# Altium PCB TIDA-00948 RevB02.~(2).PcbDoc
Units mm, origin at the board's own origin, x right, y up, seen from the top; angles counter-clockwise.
Board outline 20 x 25 mm, 2 copper layers (Top Layer, Bottom Layer), stack 1.575 mm thick; 22 components, 8 nets, 38 pads, 0 vias.
Unrouted connection lines stored in the file: 1.
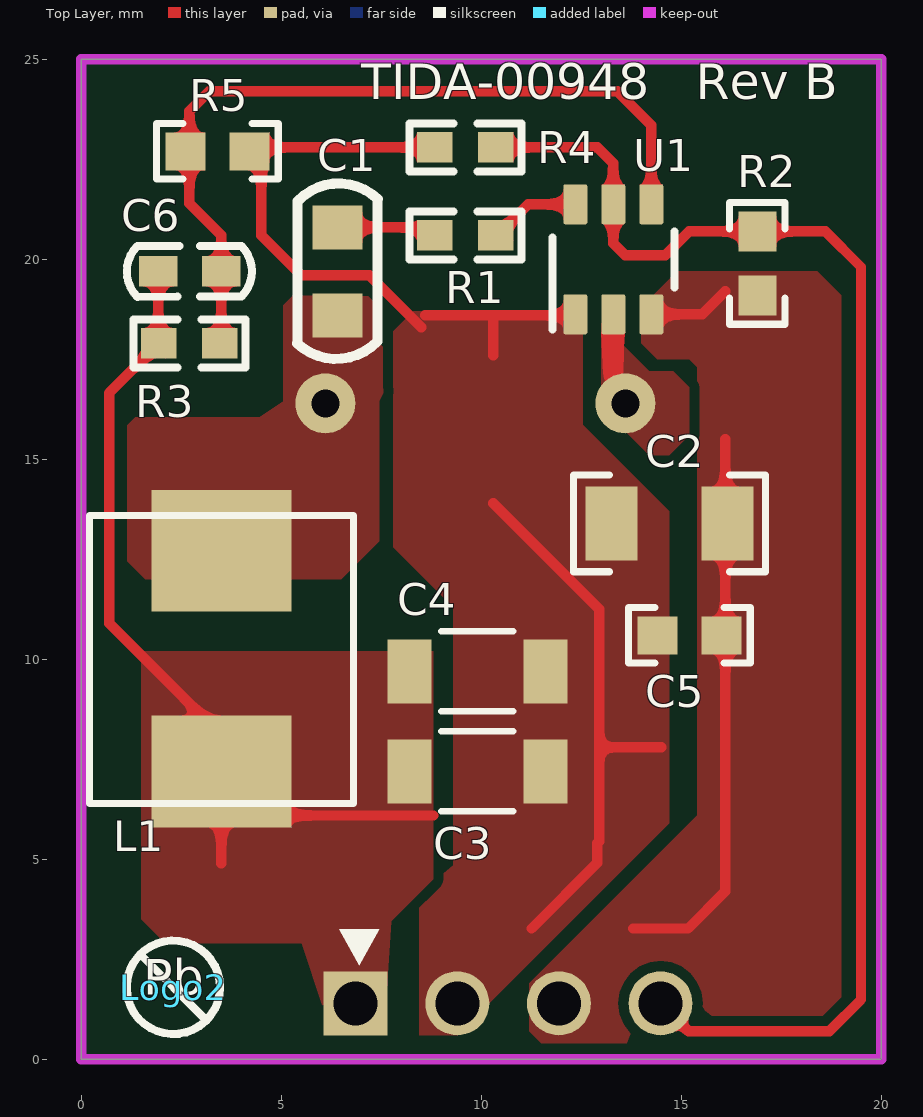
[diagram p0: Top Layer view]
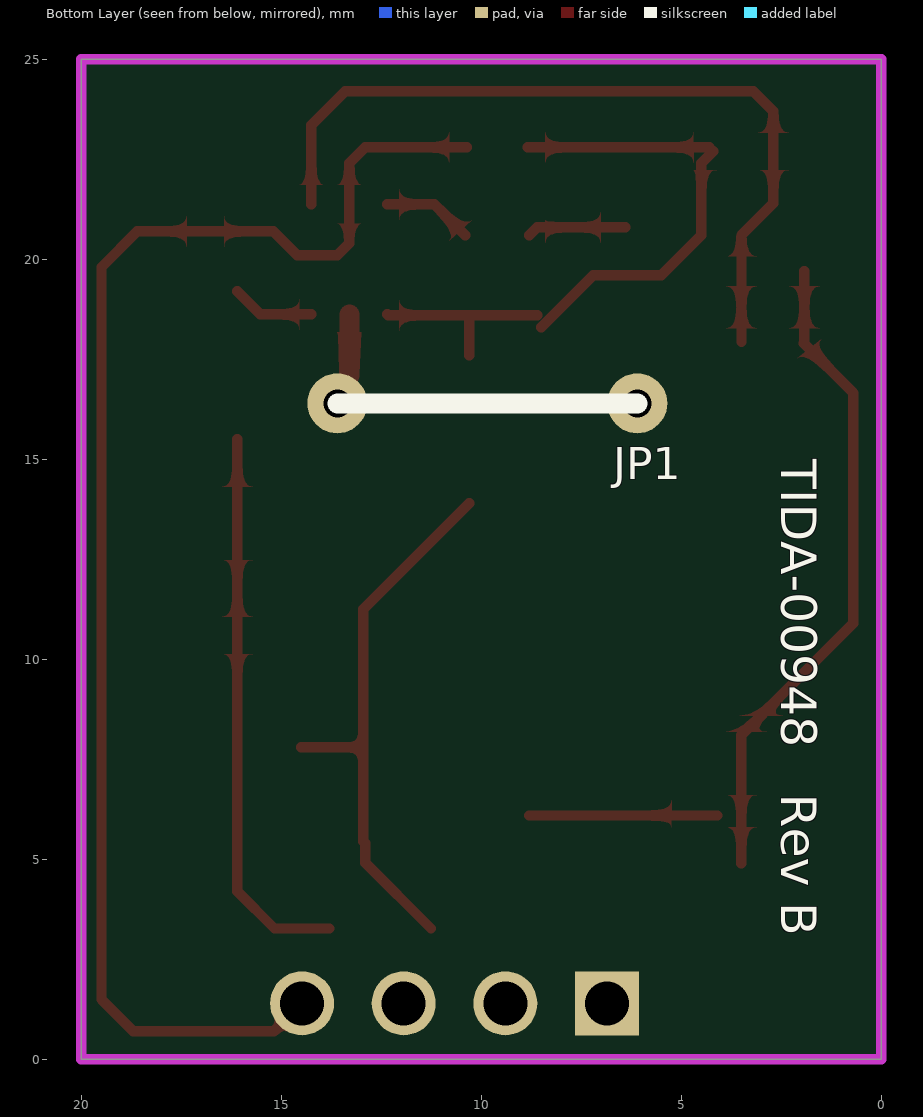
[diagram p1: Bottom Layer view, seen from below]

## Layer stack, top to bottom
Top Solder: solder mask 0.0102, Solder Resist, Dk 3.5
Top Layer: signal copper 0.0356
Dielectric1: core 1.5037, FR-4, Dk 4.8
Bottom Layer: signal copper 0.0356
Bottom Solder: solder mask 0.0102, Solder Resist, Dk 3.5

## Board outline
0,0 0,25 20,25 20,0

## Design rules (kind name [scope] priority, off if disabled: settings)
AcuteAngle [All] p1: minimum=4.50000000000000E+0001 checktracksonly=FALSE
AssemblyTestPointUsage [All] p1: valid=2
Clearance Clearance_Keepouts [((IsTrack Or IsArc) And Not InPoly) And IsFree and IsKeepOut vs ((IsTrack Or IsArc) And Not InPoly) And IsFree and IsKeepOut] p1 off: gap=0
Clearance Clearance_BoardEdge_MountingHoles [OnCopper and InComponentClass('Mounting Holes') vs IsKeepOut] p2 off: gap=1.016
Clearance Clearance_BoardEdge_Poly [OnCopper and InPoly vs IsKeepOut] p3 off: gap=0.635
Clearance Clearance_BoardEdge [OnCopper and Not InComponentClass('Logo') and not InComponentClass('FiducialMark') and not InRegion(1000,500,4000,800) and Not IsKeepout vs IsKeepOut] p4 off: gap=1.905
Clearance Clearance_Poly [InPolygon] p5 off: gap=0.635
Clearance [All] p6: gap=0.254
ComponentClearance ComponentClearance_MountingHoles_FiducialMarks [InComponentClass('Mounting Holes') vs InComponentClass('FiducialMark')] p1: gap=1.27 collisioncheckmode=3 verticalgap=0.254 showdistances=FALSE
ComponentClearance ComponentClearance_Shunt [InComponentClass('Header') vs InComponentClass('Shunt')] p2: gap=0 collisioncheckmode=3 verticalgap=0 showdistances=FALSE
ComponentClearance ComponentClearance_Logo [InComponentClass('Logo')] p3: gap=1.27 collisioncheckmode=3 verticalgap=0.254 showdistances=FALSE
ComponentClearance ComponentClearance_ScrewToNut [(HasFootprint('NY PMS 440 0025 PH')) vs (HasFootprint('Keystone_1902C'))] p4: gap=0.127 collisioncheckmode=3 verticalgap=0.254 showdistances=FALSE
ComponentClearance ComponentClearance_MountingHoles [InComponentClass('Mounting Holes')] p5: gap=6.35 collisioncheckmode=3 verticalgap=2540 showdistances=FALSE
ComponentClearance ComponentClearance_SmallPassives [HasFootprint('0201*') or HasFootprint('0402*') or HasFootprint('0508') or HasFootprint('0603*') or HasFootprint('0612') or HasFootprint('0805*') or HasFootprint('0815*') or HasFootprint('0830*') or HasFootprint('1206*') or HasFootprint('1210*') or HasFootprint('1808*') or HasFootprint('1812*') or HasFootprint('1825*') or HasFootprint('2010*') or HasFootprint('2220*') or HasFootprint('2225*') or HasFootprint('2512*') or HasFootprint('2728*') or HasFootprint('3518*') vs HasFootprint('0201*') or HasFootprint('0402*') or HasFootprint('0508') or HasFootprint('0603*') or HasFootprint('0612') or HasFootprint('0805*') or HasFootprint('0815*') or HasFootprint('0830*') or HasFootprint('1206*') or HasFootprint('1210*') or HasFootprint('1808*') or HasFootprint('1812*') or HasFootprint('1825*') or HasFootprint('2010*') or HasFootprint('2220*') or HasFootprint('2225*') or HasFootprint('2512*') or HasFootprint('2728*') or HasFootprint('3518*')] p6: gap=0.508 collisioncheckmode=3 verticalgap=0.254 showdistances=FALSE
ComponentClearance ComponentClearance_THtoSMT [IsThruComponent vs IsSMTComponent] p7: gap=2.54 collisioncheckmode=3 verticalgap=0.762 showdistances=FALSE
ComponentClearance ComponentClearance_THtoTH [IsThruComponent vs IsThruComponent] p8: gap=3 collisioncheckmode=3 verticalgap=0.762 showdistances=FALSE
ComponentClearance [All] p9: gap=1.016 collisioncheckmode=3 verticalgap=0.254 showdistances=FALSE
DiffPairsRouting [All] p1: maxlimit=2.54 minlimit=0.254 mostfreqgap=0.254 toplayer_minwidth=0.381 toplayer_maxwidth=0.381 toplayer_prefwidth=0.381 bottomlayer_minwidth=0.381 bottomlayer_maxwidth=0.381 bottomlayer_prefwidth=0.381 maxuncoupledlength=25.4
FabricationTestPointUsage TestPointUsage [All] p1: valid=2 allowmultiple=FALSE
FabricationTestpoint Testpoint [All] p1: side=3 testpointundercomponent=TRUE minsize=1.016 maxsize=2.54 preferedsize=1.524 minholesize=0 maxholesize=1.016 preferedholesize=0.813 testpointgrid=0.025 allowsidetop=TRUE allowsidebottom=TRUE usegrid=TRUE gridtolerance=0
FanoutControl Fanout_LCC [IsLCC] p1: bgadir=Out bgaviamode=Centered fanoutstyle=Auto fanoutdirection=Alternating viagrid=0.025 // Fanout_LCC (Default Rule)
FanoutControl Fanout_BGA [IsBGA] p2: bgadir=Out bgaviamode=Centered fanoutstyle=Auto fanoutdirection=Alternating viagrid=0.025 // Fanout_BGA (Default Rule)
FanoutControl Fanout_Default [All] p4: bgadir=Out bgaviamode=Centered fanoutstyle=Auto fanoutdirection=Alternating viagrid=0.025 // Fanout_Default (Default Rule)
FanoutControl Fanout_Small [(CompPinCount < 5)] p5: bgadir=Out bgaviamode=Centered fanoutstyle=Auto fanoutdirection=OutThenIn viagrid=0.025 // Fanout_Small (Default Rule)
HoleSize [All] p1: absolutevalues=TRUE maxlimit=6.375 minlimit=0.203 maxpercent=80.000 minpercent=20.000
MinimumAnnularRing MinimumAnnularRing_ThermalPadVias [IsVia and InAnyComponent] p1: minimumring=0.15
MinimumAnnularRing [All] p2: minimumring=0.229
MinimumSolderMaskSliver MinimumSolderMaskSliver_Logo [InComponentClass('Logo') vs InComponentClass('Logo')] p1: minsoldermaskwidth=0.018
MinimumSolderMaskSliver [All] p2: minsoldermaskwidth=0.1
PlaneConnect [All] p1: planeconnectstyle=Relief reliefexpansion=0.254 reliefentries=4 reliefconductorwidth=0.254 reliefairgap=0.254
PolygonConnect [All] p1: connectstyle=Direct reliefconductorwidth=0.254 reliefentries=4 polygonreliefangle="90 Angle" airgapwidth=0.254
RoutingVias ThermalPadVias [IsVia and InAnyComponent] p1: holewidth=0.2 width=0.5 viastyle="Through Hole" minholewidth=0.2 minwidth=0.5 maxholewidth=0.33 maxwidth=0.6
RoutingVias [All] p2: holewidth=0.406 width=0.864 viastyle="Through Hole" minholewidth=0.2 minwidth=0.66 maxholewidth=1.016 maxwidth=1.651
SilkToBoardRegionClearance [Not ((IsComment or IsDesignator) And (Hide <> 'False')) and not InRegion(1000,500,4000,800)] p1:
SilkToSilkClearance SilkToSilkClearance_Pb-FreeLogo [(HasFootprint('Pb-Free_Overlay_Medium') OR HasFootprint('Pb-Free_Overlay_Small')) vs (HasFootprint('Pb-Free_Overlay_Medium') OR HasFootprint('Pb-Free_Overlay_Small'))] p1: silktosilkclearance=0
SilkToSilkClearance [All] p2: silktosilkclearance=0.102
SilkToSolderMaskClearance SilkToComonentPadClearance [IsPad and InAnycomponent] p1: minsilkscreentomaskgap=0.127 clearancetoexposedcopper=TRUE
SilkToSolderMaskClearance "Silk to Solder Mask Opening" [All] p2: minsilkscreentomaskgap=0.102 clearancetoexposedcopper=FALSE
SolderMaskExpansion [All] p1: expansion=0.05
UnpouredPolygon [All] p1: allowunpoured=FALSE
Width [All] p1: maxlimit=2.54 minlimit=0.152 preferedwidth=0.254 checkconnectedcopper=TRUE
14 further rules are at their usual default settings.

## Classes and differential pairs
component class "TIDA-00948 RevA": C1 C2 C3 C4 C5 C6 JP1 L1 R1 R2 R3 R5 U1
component class Header: JP1
component class AssemblyNote: ZZ2 ZZ3 ZZ4
component class TID_Hardware: H5 H6 H7 H8 Logo2 ZZ2 ZZ3 ZZ4

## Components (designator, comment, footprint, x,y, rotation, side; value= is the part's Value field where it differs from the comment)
C1 "GRM188R71E104KA01D" C/0805/SMT1 6.4,20.7 r270 top
C2 "GRM31CR71E106KA12L" 1206 14.7,13.4 r180 top
C3 "GCM31CR71A226KE02" 1206_190 9.9,7.2 r0 top
C4 "GCM31CR71A226KE02" 1206_190 9.9,9.7 r0 top
C5 "GRM188R71E104KA01D" 0603 15.2,10.6 r180 top
C6 "06033C101KAT2A" C/0603 2.7,19.7 r0 top
H5 "1902C" Keystone_1902C -36.24,59.15 r180 bottom locked
H6 "1902C" Keystone_1902C 79.33,59.15 r180 bottom locked
H7 "1902C" Keystone_1902C -36.24,-18.32 r180 bottom locked
H8 "1902C" Keystone_1902C 79.33,-18.32 r180 bottom locked
JP1 "Comment" JUMP-7.5 6.1,16.4 r0 bottom
L1 "LPS8045B-333MRB" WE-PD-M 3.5,10 r270 top
Logo2 "Pb-Free Symbol" Pb-Free_Overlay_Small 2.3,1.8 r0 top
R1 "CRCW06030000Z0EA" r/0603 9.6,20.6 r180 top
R2 "CRCW0603510KJNEA" 0603 16.9,19.9 r270 top
R3 "CRCW0603100KFKEA" R/0603 2.7,17.9 r180 top
R4 "CRCW0603100KFKEA" R/0603 9.6,22.8 r0 top (schematic designator R3)
R5 "CRCW060313K3FKEA" 0603 3.4,22.7 r180 top
U1 "TPS54202DDCR" DDC0006A_N 13.3,20 r90 top
ZZ2 "These assemblies are ESD sensitive, ESD precautions shall be observed." AssemblyNote -36.621,73.859 r0 top
ZZ3 "These assemblies must be clean and free from flux and all contaminants. Use of no clean flux is not acceptable." AssemblyNote -36.621,71.61 r0 top
ZZ4 "These assemblies must comply with workmanship standards IPC-A-610 Class 2, unless otherwise specified." AssemblyNote -36.621,69.361 r0 top

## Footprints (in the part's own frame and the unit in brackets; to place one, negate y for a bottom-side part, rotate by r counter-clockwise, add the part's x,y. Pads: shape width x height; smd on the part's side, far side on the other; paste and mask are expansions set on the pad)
0603 [mm] "0603 from SM-752 data"
  rect 1x0.95 smd: 1(-0.8,0) 2(0.8,0)
  silkscreen extent -1.52,-0.69 1.52,0.69, body extent -0.87,-0.47 0.87,0.47, height 1
1206 [mm] "1206 from SM-752 data"
  rect 1.3x1.85 smd: 1(-1.45,0) 2(1.45,0)
  silkscreen extent -2.4,-1.21 2.4,1.21, body extent -1.7,-0.9 1.7,0.9, height 1.35
1206_190 [mm] "1206_190"
  rect 1.1x1.6 smd: 1(-1.7,0) 2(1.7,0)
  silkscreen extent -0.9,-1 0.9,1, body extent -1.75,-0.95 1.75,0.95, height 1.9
AssemblyNote [mm] "Assembly Note"
C/0603 [mil]
  rect 38x30 smd: 1(-30.52,0.06) 2(31.48,0.06)
  silkscreen extent -62,-25 62,25
C/0805/SMT1 [mm]
  rect 1.1x1.25 smd: 1(-0.1,0) 2(2.1,0)
  silkscreen extent -1.19,-1 3.19,1.01
DDC0006A_N [mm]
  rrect17% 1x0.6 smd: 1(-1.375,0.95) 2(-1.375,0) 3(-1.375,-0.95) 4(1.375,-0.95) 5(1.375,0) 6(1.375,0.95)
  silkscreen extent -1.75,-1.52 0.7,1.53, body extent -1.43,-1.48 1.43,1.49, height 0.92
JUMP-7.5 [mm]
  round 1.5 hole 0.7: 1(0,0) 2(7.5,0)
  silkscreen extent 0,0 7.5,0
Keystone_1902C [mm] "Hex Standoff, 4-40 threaded, nylon"
  body extent -3.68,-3.2 3.71,3.2, height 12.73
Pb-Free_Overlay_Small [mm]
  silkscreen extent -1.16,-1.17 1.17,1.17
r/0603 [mil]
  rect 35x30 smd: 1(-30,0) 2(30,0)
  silkscreen extent -55,-24 55,24
R/0603 [mil]
  rect 35x30 smd: 1(-30,0) 2(30,0)
  silkscreen extent -55,-24 55,24
WE-PD-M [mm] "Wurth Elektronik recommended land pattern, 2008-01-04"
  rect 2.4x3.5 smd: 1(-3.035,0) 2(3.004,0)
  silkscreen extent -3.6,-3.3 3.6,3.3, body extent -3.81,-3.84 3.81,3.79, height 4.5

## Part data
C1 C5: "CAP, CERM, 0.1 μF, 25 V, +/- 10%, X7R, 0603"
C2: "CAP, CERM, 10 μF, 25 V, +/- 10%, X7R, 1206"
C3 C4: "CAP, CERM, 22 μF, 10 V, +/- 10%, X7R, AEC-Q200 Grade 1, 1206_190"
C6: "CAP, CERM, 100 pF, 25 V, +/- 10%, X7R, 0603"
H5 H6 H7 H8: "Standoff, Hex, 0.5\"L #4-40 Nylon"
L1: "Inductor, Shielded, Ferrite, 33 μH, 1.2 A, 0.121 ohm, SMD"
Logo2: library part Pb-Free
R1: "RES, 0, 5%, 0.1 W, 0603"
R2: "RES, 510 k, 5%, 0.1 W, 0603"
R3 R4: "RES, 100 k, 1%, 0.1 W, 0603"
R5: "RES, 13.3 k, 1%, 0.1 W, 0603"
U1: "4.5-V TO 28-V INPUT, 2-A OUTPUT, EMI FRIENDLY SYNCHRONUOUS STEP-DOWN CONVERTOR, DDC0006A"
ZZ2 ZZ3 ZZ4: library part AssemblyNote

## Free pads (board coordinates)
  rect 3.5x2 smd: 0(3.5,7.6)
  rect 3.5x2.4 smd: 0(3.5,12.4)
  rect 1.6x1.6 hole 1.1: 0(6.86,1.4)
  round 1.6 hole 1.1: 0(9.4,1.4) 0(11.94,1.4) 0(14.48,1.4)

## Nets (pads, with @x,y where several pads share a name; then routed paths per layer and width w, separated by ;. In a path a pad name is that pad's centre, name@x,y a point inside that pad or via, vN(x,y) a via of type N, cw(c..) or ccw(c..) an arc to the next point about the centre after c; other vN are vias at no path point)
+5V: C3.1 C4.1 C6.1 L1.2 pad.0@3.5,7.6 pad.0@6.86,1.4 R3.2 | length 21.2
  Top Layer w0.254: R3.2@1.925,17.913 C6.1 ; R3.2 0.7,16.662 0.7,10.9 3.5,8.1 3.5,4.896 ; L1.2@4.103,6.097 8.804,6.097
EN: pad.0@14.48,1.4 R2.1 R4.2 U1.5 | length 36
  Top Layer w0.254: R4.2 12.9,22.8 13.3,22.4 U1.5 13.3,20.4 13.6,20.1 14.6,20.1 15.2,20.7 R2.1 18.6,20.7 19.492,19.808 19.492,1.492 18.7,0.7 15.18,0.7 pad.0@14.48,1.4
GND: C2.2 C3.2 C4.2 C5.2 pad.0@9.4,1.4 R4.1 R5.1 U1.1 | length 30.3
  Top Layer w0.254: R5.1 4.5,22.4 4.5,20.6 5.5,19.6 7.2,19.6 8.5,18.3 ; R5.1@4.3,22.8 R4.1 ; 8.6,18.6 12.325,18.6 U1.1 ; 10.3,13.9 12.95,11.25 12.95,7.8 ; 10.3,17.6 10.3,18.5 ; 11.258,3.27 12.9,4.912 12.9,5.4 ; 12.95,5.45 12.95,7.8 ; 14.5,7.8 12.95,7.8
NetC1_1: C1.1 R1.2 | length 2.5
  Top Layer w0.254: C1.1 8.6,20.8 R1.2@8.8,20.6
NetC1_2: C1.2 JP1.1 JP1.2 L1.1 pad.0@3.5,12.4 U1.2 | length 1.5
  Top Layer w0.5: 13.3,17.1 U1.2
NetC6_2: C6.2 R3.1 R5.2 U1.4 | length 20.2
  Top Layer w0.254: R3.1@3.5,17.938 C6.2 3.5,20.6 2.7,21.4 2.7,23.7 3.2,24.2 13.4,24.2 14.25,23.35 U1.4
NetR1_1: R1.1 U1.6 | length 2.3
  Top Layer w0.254: R1.1@10.4,20.6 11.175,21.375 U1.6
VIN: C2.1 C5.1 pad.0@11.94,1.4 R2.2 U1.3 | length 16.1
  Top Layer w0.254: 13.798,3.27 15.17,3.27 16.1,4.2 16.1,7.8 16.1,15.5 ; U1.3 15.525,18.625 16.1,19.2

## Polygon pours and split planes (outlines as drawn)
VIN on Top Layer "Top Layer-No Net 1" (solid, remove dead copper, pour order 9): 14,19 14,17.9 14.3,17.6 14.4,17.5 15.2,17.5 15.4,17.3 15.4,15.9 15.4,6.1 14.6,5.3 11.2,1.9 11.2,0.7 11.5,0.4 18.3,0.4 18.4,0.4 19,1 19,19.1 18.7,19.4 18.4,19.7 15.7,19.7 14.9,19.7 14.3,19.1
GND on Top Layer "Top Layer-No Net" (solid, remove dead copper, pour order 6): 12.535,15.865 14.7,13.7 14.7,8.2 14.7,6.2 14.7,5.9 12.8,4 9.4,0.6 8.449,0.6 8.449,4.049 9,4.6 9.3,4.858 9.3,11.3 7.8,12.8 7.8,18.2 8.3,18.7 12.535,18.7
NetC1_2 on Top Layer "Top Layer-No Net 2" (solid, remove dead copper, pour order 7): 7.45,16.45 7.45,12.95 6.5,12 1.6,12 1.15,12.45 1.15,15.85 1.35,16.05 3.75,16.05 4.45,16.05 5.05,16.45 5.05,18.85 5.3,19.1 7.35,19.073 7.35,18 7.55,17.8 7.55,15.85
NetC1_2 on Top Layer "Top Layer-No Net 3" (solid, remove dead copper, pour order 8): 13.5,18.4 13.5,17.9 13.8,17.6 14.2,17.2 14.6,17.2 14.8,17.2 15,17 15.2,16.8 15.2,16.2 15.2,15.6 14.9,15.3 14.7,15.1 14.3,15.1 14.2,15.1 13.7,15.6 13,16.3 13,17.5 13,18.4
+5V on Top Layer "Top Layer-No Net 4" (solid, remove dead copper, pour order 10): 8.8,10.2 8.8,4.5 7.75,3.45 7.621,1.547 6.021,1.356 5.507,2.9 2.1,2.9 1.5,3.5 1.5,10.2

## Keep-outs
Keep-Out Layer:
  lines w0.254: -41.447,64.23 cw(c-41.32,64.23) -41.32,64.357 ccw(c-41.32,64.23) -41.447,64.23 ; 0,0 0,25 20,25 20,0 0,0

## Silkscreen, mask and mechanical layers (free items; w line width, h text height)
Top Overlay:
  region: 6.95,2.35 7.45,3.25 6.45,3.25
  text "TIDA-00948   Rev B" at 7,23.7 h1.52
Bottom Overlay:
  text "TIDA-00948   Rev B" at 2.8,15 h1.52 r90
Top Paste:
  text ".Layer_Name" at -26.664,-45.206 h1.52
Bottom Paste:
  text ".Layer_Name" at -26.664,-45.206 h1.52
Top Solder:
  lines w0.8: 2.1,3.6 4.1,3.6 ; 3,4.8 5,4.8 ; 5.3,3.8 7.3,3.8 ; 6.25,4.75 8.25,4.75 ; 8.5,15.6 8.5,17.6 ; 8.7,12.5 8.7,14.5 ; 9.6,16.1 9.6,18.1 ; 9.7,2.4 9.7,4.4 ; 10,13 10,15 ; 10.8,3.6 10.8,5.6 ; 10.9,16.2 10.9,18.2 ; 11.6,13.09 11.6,15.09 ; 12,3.8 12,5.8 ; 13.1,6 13.1,9.3 ; 14.2,6.2 14.2,8.2 ; 16,2.2 16,5.4 ; 16.1,6.7 16.1,8.7 ; 17.1,2 17.1,5.2 ; 17.2,7.3 17.2,9.3 ; 17.2,15.5 17.2,17.5 ; 18.3,2 18.3,3.9 ; 18.3,9.3 18.3,11.3 ; 18.4,5.5 18.4,7.5 ; 18.4,13 18.4,15 ; 18.4,16.7 18.4,18.7
  lines w1: 12.9,2.5 14.9,4.5
Bottom Solder:
  text ".Layer_Name" at -26.664,-45.206 h1.52
Drill Guide:
  text ".Layer_Name" at -26.664,-45.206 h1.52
M1 Board Outline:
  lines w0.254: -41.32,-23.4 84.41,-23.4 84.41,64.23 -41.32,64.23 -41.32,-23.4
  text ".Layer_Name" at -26.664,-45.206 h1.52
M2 Board Dimensions:
  rectangle: -38.145,-33.56 -28.62,-30.385
  rectangle: -41.32,-30.385 -38.145,-27.21
  lines w0.178: -41.32,-30.385 -15.92,-30.385 ; -38.145,-33.56 -38.145,-27.21 ; -34.97,-33.56 -34.97,-27.21 ; -28.62,-33.56 -28.62,-27.21 ; -22.27,-33.56 -22.27,-27.21 ; -41.32,-33.56 -41.32,-27.21 -15.92,-27.21 -15.92,-33.56 -41.32,-33.56
  text ".Layer_Name" at -26.664,-45.206 h1.52
M3 3D STEP Top:
  text ".Layer_Name" at -26.664,-45.206 h1.52
M4 3D STEP Bottom:
  text ".Layer_Name" at -26.664,-45.206 h1.52
M5 Assembly Top:
  lines w0.254: -48.737,-47.026 118.903,-47.026 ; -48.737,-41.862 118.954,-41.862 ; -48.737,-36.697 -48.737,-52.191 52.99,-52.191 118.954,-52.191 118.954,-36.697 -48.724,-36.697 -48.724,-52.191 -8.706,-52.191 ; 13.874,-52.191 13.874,-36.697 ; 46.056,-41.862 46.056,-36.697 ; 67.392,-41.862 67.392,-36.697 ; 83.191,-52.356 83.191,-47.204
  text "COMPONENTS MARKED 'DNP' SHOULD NOT BE POPULATED." at -12.021,-31.49 h1.52
  text "ASSEMBLY VARIANT:" at -12.034,-34.424 h1.52
  text ".VariantName" at 14.281,-34.424 h1.52
  text "PCB VIEWED FROM TOP SIDE" at -47.124,-40.054 h1.52
  text "BOARD #:" at 15.779,-40.054 h1.52
  text ".PRJ_Number" at 29.635,-40.054 h1.52
  text "REV:" at 51.085,-40.054 h1.52
  text ".PCB_Rev" at 58.489,-40.054 h1.52
  text "SVN REV:" at 72.37,-40.054 h1.52
  text ".VersionControl_RevNumber" at 85.223,-40.054 h1.52
  text "TID #:" at 15.779,-45.219 h1.52
  text ".TID" at 29.635,-45.219 h1.52
  text "PLOT NAME =" at -47.124,-50.434 h1.52
  text ".plot_File_Name" at -26.664,-50.434 h1.52
  text "GENERATED    :" at 15.83,-50.434 h1.52
  text ".Print_Date" at 37.915,-50.434 h1.52
  text ".Print_Time" at 56.432,-50.434 h1.52
  text "TEXAS INSTRUMENTS" at 88.55,-50.434 h1.52
M6 Assembly Bottom:
  lines w0.254: -48.75,-41.874 118.941,-41.874 ; -48.699,-47.039 118.941,-47.039 ; -12.986,-52.369 -12.986,-47.217 ; 2.812,-41.874 2.812,-36.71 ; 24.148,-41.874 24.148,-36.71 ; 56.33,-52.204 56.33,-36.71 ; 78.911,-52.204 118.929,-52.204 118.929,-36.71 -48.75,-36.71 -48.75,-52.204 17.214,-52.204 118.941,-52.204 118.941,-36.71
  text "COMPONENTS MARKED 'DNP' SHOULD NOT BE POPULATED." at 113.671,-31.477 h1.52
  text ".VariantName" at 87.153,-34.424 h1.52
  text "ASSEMBLY VARIANT:" at 113.544,-34.424 h1.52
  text ".VersionControl_RevNumber" at -15.018,-40.067 h1.52
  text "SVN REV:" at -2.166,-40.067 h1.52
  text ".PCB_Rev" at 11.715,-40.067 h1.52
  text "REV:" at 19.119,-40.067 h1.52
  text ".PRJ_Number" at 40.57,-40.067 h1.52
  text "BOARD #:" at 54.425,-40.067 h1.52
  text "PCB VIEWED FROM BOTTOM SIDE" at 117.328,-40.067 h1.52
  text ".TID" at 40.57,-45.231 h1.52
  text "TID #:" at 54.425,-45.231 h1.52
  text "TEXAS INSTRUMENTS" at -18.346,-50.447 h1.52
  text ".Print_Time" at 13.773,-50.447 h1.52
  text ".Print_Date" at 32.289,-50.447 h1.52
  text "GENERATED    :" at 54.374,-50.447 h1.52
  text ".plot_File_Name" at 96.869,-50.447 h1.52
  text "PLOT NAME =" at 117.328,-50.447 h1.52
M9 Title Sheet:
  drawing of 57 lines, arcs and shapes, not listed
  text "1" at -22.528,180.727 h1.78
  text "2" at 40.862,180.727 h1.78
  text "3" at 104.091,180.727 h1.78
  text "4" at 167.76,180.727 h1.78
  text "5" at 231.235,180.727 h1.78
  text "6" at 294.862,180.727 h1.78
  text "A" at -51.899,151.695 h1.78
  text "A" at 324.021,151.695 h1.78
  text "B" at -51.899,91.243 h1.78
  text "B" at 324.021,91.243 h1.78
  text "C" at -51.899,30.918 h1.78
  text "C" at 324.021,30.918 h1.78
  text "PROJECT TITLE:" at 246.805,-16.351 h1.14
  text "TIDA-00948" at 248.075,-19.738 h1.78
  text "DESIGNED FOR:" at 246.805,-23.997 h1.14
  text ".PRJ_Customer" at 248.075,-27.553 h1.78
  text "D" at -51.899,-29.28 h1.78
  text "D" at 324.021,-29.28 h1.78
  text "FILE NAME:" at 246.805,-31.617 h1.14
  text ".PCB_File_Name_No_Path" at 248.075,-34.665 h1.78
  text "Texas Instruments (TI) and/or its licensors do not warrant the accuracy or completeness of this specification" at 120.58,-38.776 h1.14
  text "ENGINEER:" at 246.805,-38.983 h1.14
  text "LAYOUT BY:" at 285.032,-38.983 h1.14
  text "or any information contained therein. TI and/or its licensors do not warrant that this design will meet" at 119.437,-41.637 h1.14
  text "Jason Tao" at 248.075,-42.92 h1.78
  text "Jason Tao" at 286.315,-42.92 h1.78
  text "the specifications, will be suitable for your application or fit for any particular purpose, or will operate in" at 119.437,-44.499 h1.14
  text ".Layer_Name" at -26.664,-45.206 h1.52
  text "ALTIUM DESIGNER VERSION:" at 285.032,-46.857 h1.14
  text "an implementation. TI and/or its licensors do not warrant that the design is production worthy. You should" at 119.437,-47.361 h1.14
  text "completely validate and test your design implementation to confirm the system functionality for your application." at 120.58,-50.222 h1.14
  text ".print_Scale" at 248.075,-50.243 h1.78
  text ".Application_BuildNumber" at 286.315,-50.243 h1.78
  text "1" at -22.528,-55.493 h1.78
  text "2" at 40.862,-55.493 h1.78
  text "3" at 104.091,-55.493 h1.78
  text "4" at 167.76,-55.493 h1.78
  text "5" at 231.235,-55.493 h1.78
  text "6" at 294.862,-55.493 h1.78
M10 Fab Notes:
  drawing of 173 lines, arcs and shapes, not listed
  text "DESIGN INFORMATION" at 273.056,134.105 h1.52
  text "MIN. TRACK WIDTH:" at 256.684,129.533 h1.52
  text "8" at 284.529,129.533 h1.52
  text "MIL" at 288.46,129.533 h1.52
  text "MIN. CLEARANCE:" at 256.684,126.181 h1.52
  text "0.2" at 283.005,126.181 h1.52
  text "mm" at 288.46,126.181 h1.52
  text "MIN. VIA PAD SIZE:" at 256.684,122.828 h1.52
  text "24" at 283.767,122.828 h1.52
  text "MIL" at 288.46,122.828 h1.52
  text "0.05mm (2MIL)" at 274.337,119.228 h1.52
  text "MINIMUM ANNULAR RING" at 248.322,119.12 h1.52
  text "EXTERNAL" at 292.321,119.12 h1.52
  text "PER" at 253.402,116.122 h1.52
  text "IPC-D-275 CLASS 2 LEVEL C" at 258.99,116.122 h1.52
  text "MIL, HOLES" at 296.791,113.27 h1.52
  text "+/-" at 286.823,113.252 h1.52
  text "+/-" at 308.514,113.252 h1.52
  text "REGISTRATION TOLERANCES:" at 248.322,113.125 h1.52
  text "METAL" at 278.796,113.125 h1.52
  text "5" at 293.432,113.125 h1.52
  text "3" at 314.59,113.125 h1.52
  text "MIL" at 317.543,113.125 h1.52
  text "+/-" at 308.514,110.255 h1.52
  text "HOLE SIZE TOLERANCE (UNLESS OTHERWISE SPECIFIED):" at 248.322,110.128 h1.52
  text "3" at 314.59,110.128 h1.52
  text "MIL" at 317.543,110.128 h1.52
  text "MATERIAL:" at 246.423,104.808 h1.52
  text "FR-4 High Tg" at 271.479,101.243 h1.52
  text "FR-408" at 257.116,101.025 h1.52
  text "OTHER" at 294.911,101.025 h1.52
  text "X" at 267.544,100.933 h1.52
  text "62 MIL (1.6mm) +/-10%" at 265.247,96.892 h1.52
  text "THICKNESS:" at 248.322,96.784 h1.52
  text "X" at 261.991,96.784 h1.52
  text "OTHER" at 297.883,96.784 h1.52
  text "TOLERANCE:" at 248.322,92.77 h1.52
  text "X" at 269.64,92.77 h1.52
  text "ANSI IPC-6012 TYPE 3 CLASS 2" at 274.389,92.77 h1.52
  text "OTHER +/-" at 274.388,88.808 h1.52
  text "BOW & TWIST:" at 248.322,84.82 h1.52
  text "X" at 269.64,84.82 h1.52
  text "ANSI IPC-6012 TYPE 3 CLASS 2" at 274.389,84.82 h1.52
  text "OTHER +/-" at 274.388,80.794 h1.52
  text "DRILLING:" at 246.423,77.276 h1.52
  text "REFERENCE:" at 248.322,74.305 h1.52
  text "X" at 264.787,74.305 h1.52
  text "AS SHOWN" at 269.537,74.305 h1.52
  text "X" at 287.672,74.305 h1.52
  text "NC_DRILL FILES" at 291.152,74.305 h1.52
  text "PTH MIN COPPER THICKNESS:" at 248.322,70.291 h1.52
  text "X" at 282.618,70.291 h1.52
  text "1MIL" at 286.098,70.291 h1.52
  text "OTHER" at 298.721,70.291 h1.52
  text "BOARD FINISH:" at 246.423,66.253 h1.52
  text "SILKSCREEN:" at 250.365,63.256 h1.52
  text "X" at 274.464,63.256 h1.52
  text "TOP" at 277.665,63.256 h1.52
  text "X" at 287.418,63.256 h1.52
  text "BOTTOM" at 290.644,63.256 h1.52
  text "SILKSCREEN COLOR:" at 250.365,59.014 h1.52
  text "X" at 274.438,59.014 h1.52
  text "WHITE" at 277.665,59.014 h1.52
  text "OTHER" at 290.644,59.014 h1.52
  text "X" at 277.766,54.97 h1.52
  text "GREEN" at 280.992,54.97 h1.52
  text "OTHER" at 296.689,54.97 h1.52
  text "SOLDER RESIST COLOR:" at 250.365,54.696 h1.52
  text "X" at 277.766,50.652 h1.52
  text "MATTE" at 280.992,50.652 h1.52
  text "SEMI-GLOSS" at 296.678,50.636 h1.52
  text "IMMERSION GOLD (ENIG)" at 273.372,45.864 h1.52
  text "ENEPIG" at 307.346,45.78 h1.52
  text "SURFACE FINISH:" at 246.423,45.755 h1.52
  text "X" at 268.624,45.755 h1.52
  text "IMM. TIN/SILVER OR EQUIV" at 254.793,41.767 h1.52
  text "OTHER" at 291.152,41.767 h1.52
  text "ARRAY/PANEL:" at 246.423,37.221 h1.52
  text "CUT AND TRIM PER M1 BOARD OUTLINE" at 273.372,37.112 h1.52
  text "N.C. ROUTE" at 273.372,33.258 h1.52
  text "X" at 290.619,33.258 h1.52
  text "V. SCORE" at 295.369,33.258 h1.52
  text "CERTIFICATION:" at 246.423,29.778 h1.52
  text "MATERIALS AND WORKMANSHIP FOR ALL PCBS" at 264.838,29.778 h1.52
  text "TO MEET OR EXCEED THE REQUIREMENTS OF:" at 264.838,27.289 h1.52
  text "X" at 255.351,23.822 h1.52
  text "ANSI IPC-A-600F CLASS ->" at 258.882,23.822 h1.52
  text "X" at 300.514,23.822 h1.52
  text "2" at 303.535,23.822 h1.52
  text "1" at 295.534,23.784 h1.52
  text "3" at 312.526,23.784 h1.52
  text "X" at 276.028,19.771 h1.52
  text "RoHS" at 279.506,19.771 h1.52
  text "OTHER" at 295.874,19.771 h1.52
  text "PER ORDER" at 305.96,19.771 h1.52
  text "ALL BOARDS MUST MEET OR EXCEED UL94-V0 REQUIREMENTS." at 247.122,15.564 h1.52
  text "PCB MUST BEAR THE UL94V-0 UL REGISTERED MATERIAL ID NUMBER" at 247.122,12.516 h1.52
  text "ADDITIONAL REQUIREMENTS:" at 246.423,8.112 h1.52
  text "MICROSECTION:" at 248.322,5.191 h1.52
  text "YES" at 271.328,5.191 h1.52
  text "REQUIRED" at 293.21,1.225 h1.52
  text "BARE BOARD ELEC. TEST:" at 248.322,1.153 h1.52
  text "NONE" at 281.488,1.153 h1.52
  text "X" at 289.984,1.153 h1.52
  text "PER ORDER" at 308.246,1.153 h1.52
  text ".Layer_Name" at -26.664,-45.206 h1.52
M11 Gerber Information:
  lines w0.254: -48.737,-47.026 118.903,-47.026 ; -48.737,-41.862 118.954,-41.862 ; -48.737,-36.697 -48.737,-52.191 52.99,-52.191 118.954,-52.191 118.954,-36.697 -48.724,-36.697 -48.724,-52.191 -8.706,-52.191 ; 13.874,-52.191 13.874,-36.697 ; 46.056,-41.862 46.056,-36.697 ; 67.392,-41.862 67.392,-36.697 ; 83.191,-52.356 83.191,-47.204
  text "ALL ARTWORK VIEWED FROM TOP SIDE" at -47.124,-40.054 h1.52
  text "BOARD #:" at 15.779,-40.054 h1.52
  text ".PRJ_Number" at 29.635,-40.054 h1.52
  text "REV:" at 51.085,-40.054 h1.52
  text ".PCB_Rev" at 58.489,-40.054 h1.52
  text "SVN REV:" at 72.37,-40.054 h1.52
  text ".VersionControl_RevNumber" at 85.223,-40.054 h1.52
  text "LAYER NAME =" at -47.124,-45.206 h1.52
  text "TID #:" at 15.779,-45.219 h1.52
  text ".TID" at 29.635,-45.219 h1.52
  text "PLOT NAME =" at -47.124,-50.434 h1.52
  text ".plot_File_Name" at -26.664,-50.434 h1.52
  text "GENERATED    :" at 15.83,-50.434 h1.52
  text ".Print_Date" at 37.915,-50.434 h1.52
  text ".Print_Time" at 56.432,-50.434 h1.52
  text "TEXAS INSTRUMENTS" at 88.55,-50.434 h1.52
M12 Stackup:
  drawing of 191 lines, arcs and shapes, not listed
  text "Layer" at 207.361,175.482 h1.52
  text "Name" at 217.772,175.482 h1.52
  text "Material" at 241.388,175.482 h1.52
  text "Thickness" at 263.226,175.482 h1.52
  text "Constant" at 279.732,175.482 h1.52
  text "Board Layer Stack" at 294.206,175.482 h1.52
  text "1" at 207.361,172.434 h1.52
  text "Top Overlay" at 217.772,172.434 h1.52
  text "2" at 207.361,169.386 h1.52
  text "Top Solder" at 217.772,169.386 h1.52
  text "Solder Resist" at 241.388,169.386 h1.52
  text "0.40mil" at 263.226,169.386 h1.52
  text "3.5" at 279.732,169.386 h1.52
  text "3" at 207.361,166.338 h1.52
  text "Top Layer" at 217.772,166.338 h1.52
  text "Copper" at 241.388,166.338 h1.52
  text "1.40mil" at 263.226,166.338 h1.52
  text "4" at 207.361,163.29 h1.52
  text "Dielectric1" at 217.772,163.29 h1.52
  text "FR-4" at 241.388,163.29 h1.52
  text "59.20mil" at 263.226,163.29 h1.52
  text "4.8" at 279.732,163.29 h1.52
  text "5" at 207.361,160.242 h1.52
  text "Bottom Layer" at 217.772,160.242 h1.52
  text "Copper" at 241.388,160.242 h1.52
  text "1.40mil" at 263.226,160.242 h1.52
  text "6" at 207.361,157.194 h1.52
  text "Bottom Solder" at 217.772,157.194 h1.52
  text "Solder Resist" at 241.388,157.194 h1.52
  text "0.40mil" at 263.226,157.194 h1.52
  text "3.5" at 279.732,157.194 h1.52
  text "7" at 207.361,154.146 h1.52
  text "Bottom Overlay" at 217.772,154.146 h1.52
  text ".Layer_Name" at -26.664,-45.206 h1.52
M13 Component Bodies Top:
  text ".Layer_Name" at -26.664,-45.206 h1.52
M14 Component Bodies Bottom:
  text ".Layer_Name" at -26.664,-45.206 h1.52
M15 Courtyards Top:
  text ".Layer_Name" at -26.664,-45.206 h1.52
M16 Courtyards Bottom:
  text ".Layer_Name" at -26.664,-45.206 h1.52
Drill Drawing:
  circle w0.025: c100.227,54.622 r0.632
  lines w0.025: 99.595,59.047 100.859,59.047 100.227,57.782 99.595,59.047
  lines w0.305: 97.872,52.852 151.67,52.852 ; 97.872,60.437 151.67,60.437 ; 107.279,49.059 107.279,64.23 ; 116.347,49.059 116.347,64.23 ; 133.151,49.059 133.151,64.23 ; 140.368,49.059 140.368,64.23 ; 97.872,49.059 151.67,49.059 151.67,64.23 97.872,64.23 97.872,49.059
  text "Symbol" at 100.148,61.575 h1.83
  text "Quantity" at 108.417,61.575 h1.83
  text "Finished Hole Size" at 117.485,61.575 h1.83
  text "Plated" at 134.289,61.575 h1.83
  text "Hole Type" at 141.506,61.575 h1.83
  text "2" at 108.417,57.782 h1.52
  text "27.56mil (0.700mm)" at 117.485,57.782 h1.52
  text "PTH" at 134.289,57.782 h1.52
  text "Round" at 141.506,57.782 h1.52
  text "4" at 108.417,53.99 h1.52
  text "43.31mil (1.100mm)" at 117.485,53.99 h1.52
  text "PTH" at 134.289,53.99 h1.52
  text "Round" at 141.506,53.99 h1.52
  text "6 Total" at 108.417,50.197 h1.52
  text ".Layer_Name" at -26.664,-45.206 h1.52

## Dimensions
-41.32,-23.4 to 0,25 on M2 Board Dimensions
-41.32,-23.4 to 20,0 on M2 Board Dimensions
-41.32,-33.56 to -15.92,-33.56 on M2 Board Dimensions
